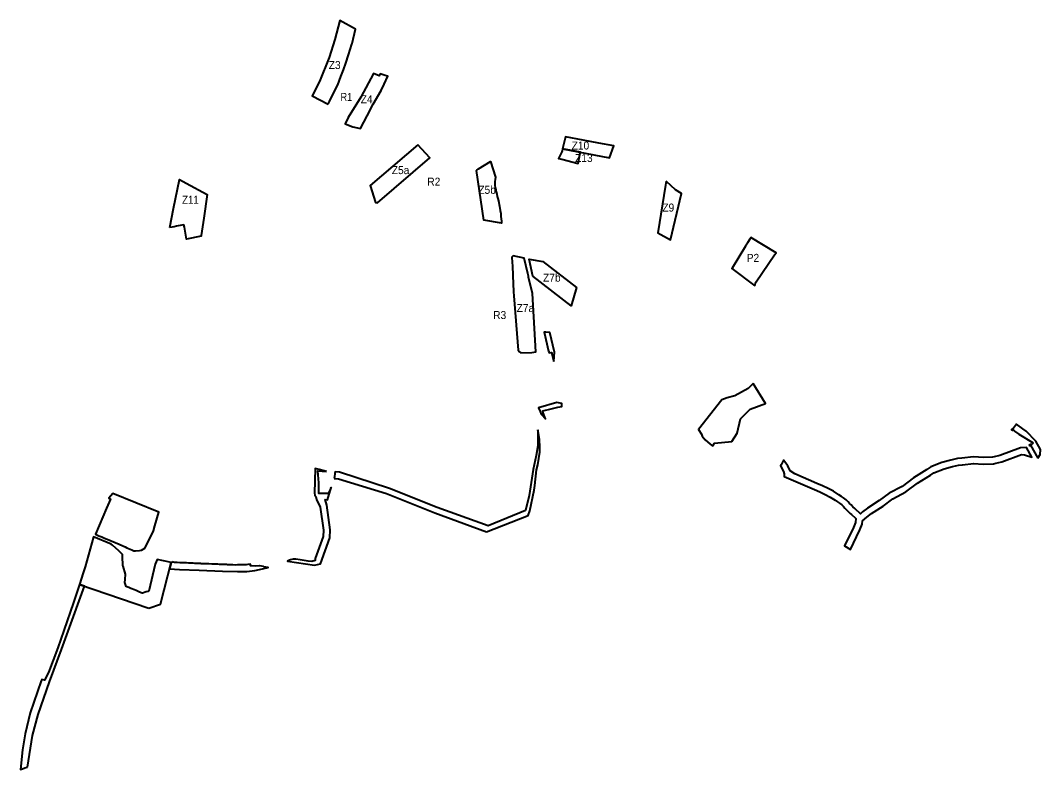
# Model space of a CAD drawing. Extents: x -555426 to -553131, y -1186725 to -1183160.
# Drawn here: x -555426 to -553131, y -1186725 to -1185042 of the extents above; entities that cross this region are included whole.
import ezdxf
from ezdxf.enums import TextEntityAlignment as Align

# ---------------------------------------------------------------- set-up
doc = ezdxf.new("R2010")
doc.units = 0
doc.header["$LTSCALE"] = 7.2
doc.header["$PDMODE"] = 32
doc.header["$PDSIZE"] = 3.6
for name, color, linetype, lineweight in [('12', 7, 'Continuous', 40), ('17', 7, 'Continuous', 40), ('2', 7, 'Continuous', 40), ('48', 7, 'Continuous', 40), ('6', 7, 'Continuous', 40), ('62', 7, 'Continuous', 25), ('8', 7, 'Continuous', 40)]:
    doc.layers.add(name, color=color, linetype=linetype, lineweight=lineweight)
for name, color, linetype in [('59', 7, 'Continuous'), ('60', 7, 'Continuous'), ('61', 7, 'Continuous')]:
    doc.layers.add(name, color=color, linetype=linetype)

msp = doc.modelspace()

# ---------------------------------------------------------------- linework, layer by layer
at = {"layer": '12'}
msp.add_lwpolyline([(-553973.359, -1185402.641), (-553974.35, -1185411.9), (-553991.445, -1185519.302), (-553963.43, -1185534.75), (-553938.9, -1185430.55), (-553951.92, -1185422.15), (-553972.449, -1185403.469)], close=True, dxfattribs=at)
at = {"layer": '17'}
msp.add_lwpolyline([(-554205.92, -1185330.047), (-554207, -1185334.66), (-554207.96, -1185336.64), (-554215.313, -1185351.817), (-554207.47, -1185353.77), (-554170.793, -1185362.901), (-554167.012, -1185343.092), (-554166.009, -1185337.836)], close=True, dxfattribs=at)
at = {"layer": '2'}
for points in [[(-554733.51, -1185230.02), (-554730.2, -1185223.52), (-554717.59, -1185197.71), (-554711.77, -1185186.23), (-554704.88, -1185167.56), (-554699.12, -1185152.43), (-554693.52, -1185137.73), (-554687.65, -1185119.22), (-554679.93, -1185094.89), (-554679.52, -1185093.4), (-554671.85, -1185061.39), (-554707.18, -1185041.55), (-554718.485, -1185084.142), (-554731.329, -1185124.63), (-554753.057, -1185179.2), (-554769.052, -1185211.233)], [(-554688.42, -1185259.67), (-554694.99, -1185274.23), (-554677.59, -1185280.44), (-554660.25, -1185284.19), (-554645.24, -1185255.79), (-554631.94, -1185230), (-554613.87, -1185198.73), (-554607.1, -1185184.92), (-554598.76, -1185166.79), (-554605.12, -1185165.73), (-554616.11, -1185161.44), (-554616.48, -1185161.3), (-554618.25, -1185166.48), (-554630.97, -1185160.97), (-554660.04, -1185213.75)], [(-554531.777, -1185321.491), (-554638.923, -1185412.788), (-554627.182, -1185450.638), (-554622.556, -1185451.394), (-554504.308, -1185350.637)], [(-554399.867, -1185378.779), (-554398.64, -1185377.82), (-554394.81, -1185374.96), (-554368.27, -1185358.89), (-554357.24, -1185393.87), (-554357.73, -1185399.4), (-554358.1, -1185403.56), (-554358.55, -1185407.8), (-554358.24, -1185412.39), (-554357.86, -1185417.02), (-554356.48, -1185422.06), (-554355.39, -1185427.08), (-554354.3, -1185432.1), (-554353.02, -1185437.14), (-554351.77, -1185442.03), (-554350.5, -1185447.06), (-554348.02, -1185459.19), (-554346.15, -1185468.55), (-554345.29, -1185475.74), (-554344.6, -1185481.98), (-554344.16, -1185487.64), (-554343.59, -1185493), (-554343.144, -1185497.196), (-554383.322, -1185490.608)], [(-554305.651, -1185782.363), (-554303.28, -1185786.68), (-554300.2, -1185788.59), (-554275.27, -1185787.98), (-554266.32, -1185786.4), (-554273.88, -1185655.23), (-554282.43, -1185618.58), (-554282.94, -1185616.37), (-554284.34, -1185610.24), (-554292.21, -1185575.92), (-554316.867, -1185570.895), (-554319.852, -1185573.671), (-554319.21, -1185586), (-554318.84, -1185593.32), (-554317.73, -1185614.65), (-554316.26, -1185651.34), (-554315.85, -1185660.44)], [(-554272.647, -1185616.49), (-554281.413, -1185578.266), (-554250.477, -1185583.069), (-554174.425, -1185641.889), (-554187.013, -1185682.721)]]:
    msp.add_lwpolyline(points, close=True, dxfattribs=at)
at = {"layer": '48'}
for p, q in [((-553147.76, -1185990.72), (-553153.84, -1185996.12)), ((-553153.84, -1185996.12), (-553136.76, -1186025.81))]:
    msp.add_line(p, q, dxfattribs=at)
for points in [[(-554225.516, -1185808.234), (-554224.11, -1185787.364), (-554234.745, -1185743.116), (-554244.07, -1185742.37), (-554247.64, -1185742.08), (-554237.39, -1185785.09)], [(-554237.39, -1185785.09), (-554235.75, -1185788.44), (-554231.18, -1185787.69), (-554225.516, -1185808.234)], [(-553777.28, -1185857.816), (-553788.665, -1185868.775), (-553818.407, -1185885.262), (-553836.143, -1185889.543), (-553848.116, -1185894.514), (-553900.68, -1185960.74), (-553893.92, -1185971.59), (-553892.19, -1185976.11), (-553885.57, -1185984.25)], [(-553825.075, -1185988.124), (-553813.195, -1185969.073), (-553806.078, -1185936.966), (-553784.191, -1185915.024), (-553749.515, -1185902.394), (-553777.28, -1185857.816)], [(-554219.04, -1185900.71), (-554260.557, -1185912.173), (-554256.71, -1185920.61), (-554254.1, -1185926.61), (-554244.35, -1185937.42), (-554249.57, -1185923.77), (-554250.31, -1185919.09), (-554231.43, -1185914.6)], [(-554231.43, -1185914.6), (-554219.41, -1185911.75), (-554216.82, -1185911.13), (-554207.981, -1185909.04), (-554207.51, -1185902.62), (-554219.04, -1185900.71)], [(-553136.76, -1186025.81), (-553131.636, -1186017.15), (-553130.875, -1186005.959), (-553141.815, -1185986.942), (-553163.584, -1185965.017), (-553170.649, -1185959.736), (-553185.396, -1185948.905), (-553193.99, -1185961.2)], [(-554261.93, -1185961.69), (-554261.867, -1185997.814), (-554265.332, -1186019.412), (-554272.29, -1186050.65), (-554281.22, -1186109.23), (-554289.524, -1186142.992), (-554373.27, -1186177.71), (-554488.13, -1186136.21), (-554595.17, -1186093.44), (-554707.698, -1186057.015), (-554717.81, -1186056.56), (-554718.22, -1186060.11), (-554719.05, -1186067.25), (-554719.544, -1186071.497)], [(-554377.29, -1186191), (-554283.71, -1186153.97), (-554279.71, -1186143.62), (-554270.02, -1186097.65), (-554268.36, -1186086.78), (-554265, -1186051.94), (-554262.02, -1186040.25), (-554257.45, -1186011.8), (-554256.93, -1185999.75), (-554257.84, -1185983.71), (-554261.93, -1185961.69)], [(-553193.99, -1185961.2), (-553189.33, -1185964.5), (-553179.63, -1185971.75), (-553147.76, -1185990.72)], [(-553885.57, -1185984.25), (-553874.36, -1185993.93), (-553868.12, -1185998.62)], [(-553868.12, -1185998.62), (-553864.032, -1185991.549), (-553825.075, -1185988.124)], [(-554737.11, -1186055.23), (-554753.62, -1186050.71), (-554762.47, -1186048.86), (-554763.69, -1186104.04), (-554763.13, -1186108.53), (-554761.3, -1186111.92), (-554759.33, -1186118.73), (-554750.96, -1186135.85), (-554743.83, -1186187.67), (-554744.21, -1186201.47), (-554762.32, -1186250.8), (-554762.42, -1186255.74), (-554769.94, -1186257.54), (-554778.46, -1186256.89), (-554796.4, -1186253.91), (-554805.74, -1186252.36), (-554812.08, -1186252.63), (-554817.93, -1186254.2), (-554820.52, -1186254.89), (-554825.122, -1186257.297), (-554764.262, -1186265.676)], [(-554764.262, -1186265.676), (-554750.84, -1186263.055), (-554729.283, -1186204.336), (-554728.802, -1186186.849), (-554736.428, -1186131.423), (-554740.112, -1186118.075), (-554734.72, -1186119), (-554726.42, -1186091.6), (-554733.53, -1186104.88), (-554754.02, -1186104.78), (-554754.21, -1186080.59), (-554756.79, -1186053.88), (-554737.11, -1186055.23)], [(-554719.544, -1186071.497), (-554710.393, -1186071.909), (-554602.25, -1186105.03), (-554493.14, -1186148.4), (-554377.29, -1186191)], [(-555084.2, -1186258.4), (-555084.7, -1186260.33), (-555086.13, -1186260.01), (-555089.854, -1186274.456)], [(-554906.96, -1186263.94), (-554913.63, -1186264.75), (-554917.47, -1186265.28), (-554919.39, -1186265.33), (-554927.11, -1186265.47), (-554932.26, -1186265.55), (-554936.56, -1186265.5), (-554937.11, -1186265.47), (-554942.03, -1186265.63), (-554947.66, -1186265.42), (-554953.66, -1186265.32), (-554959.36, -1186264.92), (-554961.69, -1186264.81), (-554964.83, -1186264.67), (-554969.85, -1186264.42), (-554976.07, -1186264.1), (-554978.07, -1186264.16), (-554981.59, -1186263.95), (-554986.25, -1186263.91), (-554987.98, -1186263.78), (-554994.91, -1186263.58), (-555001.35, -1186263.21), (-555004.22, -1186263.18), (-555007.26, -1186263.05), (-555012.37, -1186262.95), (-555013.89, -1186263.01), (-555018.64, -1186262.69), (-555020.77, -1186262.57), (-555022.88, -1186262.45), (-555027.97, -1186262.21), (-555033.35, -1186261.86), (-555037.22, -1186261.67), (-555038.25, -1186261.63), (-555042.62, -1186261.45), (-555045.15, -1186261.2), (-555047.35, -1186261.3), (-555052.31, -1186261.05), (-555057.13, -1186260.95), (-555060.21, -1186260.69), (-555061.43, -1186260.68), (-555067.24, -1186260.4), (-555072.69, -1186260.16), (-555077.96, -1186259.94), (-555079.09, -1186259.62), (-555084.2, -1186258.4)], [(-554937.275, -1186280.483), (-554916.246, -1186280.253), (-554898.31, -1186277.981), (-554881.215, -1186274.099), (-554868.43, -1186271.13), (-554869.06, -1186271.01), (-554877.64, -1186269.36), (-554878.85, -1186269.12), (-554886.77, -1186267.56), (-554887.87, -1186267.31), (-554897.58, -1186268.01), (-554907.83, -1186267.84), (-554906.96, -1186263.94)], [(-555089.854, -1186274.456), (-555067.931, -1186275.384), (-555023.659, -1186277.43), (-554970.608, -1186279.401), (-554937.275, -1186280.483)], [(-555409.6, -1186719.66), (-555398.08, -1186648.64), (-555385.52, -1186601.65), (-555360.47, -1186527.99), (-555332.87, -1186455.38), (-555317.95, -1186413.97), (-555281.216, -1186313.355), (-555292.95, -1186309.355), (-555305.75, -1186349.85), (-555327.86, -1186412.63), (-555341.32, -1186452.09), (-555362.31, -1186507.34), (-555371.26, -1186524.24), (-555374.35, -1186523.58)], [(-555374.35, -1186523.58), (-555377.44, -1186522.92), (-555378.76, -1186526.22), (-555403.3, -1186597.68)], [(-555403.3, -1186597.68), (-555414.63, -1186645.4), (-555420.53, -1186680.78), (-555425.54, -1186725.43), (-555420.84, -1186723.67), (-555415.22, -1186721.67), (-555409.6, -1186719.66)]]:
    msp.add_lwpolyline(points, dxfattribs=at)
for points in [[(-553548.02, -1186159.66), (-553546.182, -1186161.261), (-553546.991, -1186169.987), (-553551.543, -1186181.231), (-553571.668, -1186222.815), (-553558.79, -1186230.64), (-553551.72, -1186216.33), (-553544.71, -1186202.05), (-553537.64, -1186186.86), (-553532.26, -1186173.57), (-553531.6, -1186166.45), (-553521.79, -1186158.06), (-553511.19, -1186150.03), (-553485.32, -1186133.04), (-553463.3, -1186117.12), (-553433.95, -1186101.46), (-553408.08, -1186081.8), (-553378.55, -1186063.63), (-553370.87, -1186058.18), (-553348.08, -1186049.28), (-553328.68, -1186044.22), (-553315.27, -1186040.84), (-553306.3, -1186040.1), (-553306.3, -1186040.1), (-553281.66, -1186037.48), (-553281.66, -1186037.48), (-553259.77, -1186038.75), (-553237.04, -1186038), (-553231.86, -1186036.89), (-553218.26, -1186033.91), (-553173.99, -1186017.29), (-553167.22, -1186018.11), (-553150.76, -1186023.24), (-553162.91, -1186001.77), (-553175.828, -1186001.958), (-553222.523, -1186019.488), (-553235.037, -1186022.23), (-553238.873, -1186023.052), (-553259.583, -1186023.736), (-553282.021, -1186022.434), (-553307.71, -1186025.165), (-553317.736, -1186025.993), (-553332.406, -1186029.69), (-553352.717, -1186034.988), (-553378.046, -1186044.879), (-553386.83, -1186051.112), (-553416.569, -1186069.411), (-553442.07, -1186088.791), (-553471.261, -1186104.366), (-553493.836, -1186120.687), (-553519.846, -1186137.769), (-553531.202, -1186146.372), (-553535.863, -1186150.358), (-553538.103, -1186148.406), (-553546.022, -1186141.348), (-553548.683, -1186138.882), (-553553.043, -1186134.503), (-553557.145, -1186130.6), (-553560.554, -1186127.153), (-553563.838, -1186123.82), (-553568.263, -1186119.334), (-553574.069, -1186114.956), (-553578.7, -1186111.427), (-553584.623, -1186107.599), (-553596.515, -1186099.928), (-553608.823, -1186093.668), (-553621.239, -1186087.362), (-553633.865, -1186082.054), (-553683.475, -1186060.759), (-553694.198, -1186053.632), (-553699.051, -1186042.658), (-553709.22, -1186029.91), (-553714.54, -1186040.11), (-553715.99, -1186043.02), (-553709.24, -1186055.23), (-553707.92, -1186060.73), (-553707.78, -1186066.65), (-553639.73, -1186095.86), (-553627.55, -1186100.98), (-553615.62, -1186107.04), (-553604, -1186112.95), (-553592.76, -1186120.2), (-553587.33, -1186123.71), (-553583.13, -1186126.91), (-553578.17, -1186130.65), (-553574.52, -1186134.35), (-553571.23, -1186137.69), (-553567.65, -1186141.31), (-553563.53, -1186145.23), (-553559.1, -1186149.68), (-553556.11, -1186152.45)], [(-555185.99, -1186226.72), (-555175.06, -1186231.77), (-555170.16, -1186234.03), (-555166.5, -1186233.72), (-555157.32, -1186232.94), (-555153.01, -1186232.57), (-555146, -1186227.85), (-555144.69, -1186226.97), (-555126.25, -1186188.5), (-555123.11, -1186177.66), (-555114.26, -1186147.16), (-555217.36, -1186104.58), (-555226.45, -1186115.68), (-555223.12, -1186117.41), (-555232.18, -1186137.72), (-555256.91, -1186196.5), (-555248.77, -1186199.76), (-555242.74, -1186202.33), (-555236.71, -1186204.91), (-555230.2, -1186207.64), (-555212.56, -1186215.1), (-555203.72, -1186218.85), (-555194.89, -1186222.61), (-555190.05, -1186224.85)], [(-555136.764, -1186362.594), (-555110.731, -1186353.98), (-555101.91, -1186321.23), (-555086.13, -1186260.01), (-555093.4, -1186258.38), (-555100.06, -1186256.89), (-555107.79, -1186255.16), (-555114.53, -1186253.65), (-555117.88, -1186252.9), (-555122.79, -1186264.03), (-555136.85, -1186324.41), (-555138.36, -1186325.06), (-555142.52, -1186326.28), (-555150.68, -1186328.68), (-555151.71, -1186328.98), (-555157.95, -1186326.36), (-555165.36, -1186323.24), (-555169.27, -1186321.6), (-555177.22, -1186318.25), (-555181.71, -1186316.36), (-555186.26, -1186314.45), (-555187.71, -1186313.84), (-555190.76, -1186304.59), (-555190.1, -1186297.86), (-555188.93, -1186285.88), (-555194.7, -1186268.11), (-555195.22, -1186267.63), (-555195.64, -1186245.84), (-555195.72, -1186241.89), (-555197.18, -1186240.55), (-555204.2, -1186234.11), (-555218.31, -1186221.15), (-555221.4, -1186218.64), (-555261.28, -1186202.32), (-555279.68, -1186269.64), (-555284.72, -1186283.32), (-555292.95, -1186309.355)]]:
    msp.add_lwpolyline(points, close=True, dxfattribs=at)
for p in [(-553193.99, -1185961.2), (-553153.84, -1185996.12)]:
    msp.add_point(p, dxfattribs=at)
at = {"layer": '6'}
msp.add_lwpolyline([(-554205.92, -1185330.047), (-554100.379, -1185350.644), (-554090.82, -1185323.71), (-554124.84, -1185317.69), (-554160.01, -1185310.95), (-554199.59, -1185303)], close=True, dxfattribs=at)
at = {"layer": '62'}
for points in [[(-554707.18, -1185041.55), (-554671.85, -1185061.39), (-554679.52, -1185093.4), (-554679.93, -1185094.89), (-554687.65, -1185119.22), (-554693.52, -1185137.73), (-554699.12, -1185152.43), (-554704.88, -1185167.56), (-554711.77, -1185186.23), (-554717.59, -1185197.71), (-554730.2, -1185223.52), (-554733.51, -1185230.02), (-554769.052, -1185211.233), (-554753.057, -1185179.2), (-554731.329, -1185124.63), (-554718.485, -1185084.142)], [(-554677.59, -1185280.44), (-554660.25, -1185284.19), (-554645.24, -1185255.79), (-554631.94, -1185230), (-554613.87, -1185198.73), (-554607.1, -1185184.92), (-554598.76, -1185166.79), (-554605.12, -1185165.73), (-554616.11, -1185161.44), (-554616.48, -1185161.3), (-554618.25, -1185166.48), (-554630.97, -1185160.97), (-554660.04, -1185213.75), (-554688.42, -1185259.67), (-554694.99, -1185274.23)], [(-554205.92, -1185330.047), (-554100.379, -1185350.644), (-554090.82, -1185323.71), (-554124.84, -1185317.69), (-554160.01, -1185310.95), (-554199.59, -1185303)], [(-554531.777, -1185321.491), (-554638.923, -1185412.788), (-554627.182, -1185450.638), (-554622.556, -1185451.394), (-554504.308, -1185350.637)], [(-554399.867, -1185378.779), (-554398.64, -1185377.82), (-554394.81, -1185374.96), (-554368.27, -1185358.89), (-554357.24, -1185393.87), (-554357.73, -1185399.4), (-554358.1, -1185403.56), (-554358.55, -1185407.8), (-554358.24, -1185412.39), (-554357.86, -1185417.02), (-554356.48, -1185422.06), (-554355.39, -1185427.08), (-554354.3, -1185432.1), (-554353.02, -1185437.14), (-554351.77, -1185442.03), (-554350.5, -1185447.06), (-554348.02, -1185459.19), (-554346.15, -1185468.55), (-554345.29, -1185475.74), (-554344.6, -1185481.98), (-554344.16, -1185487.64), (-554343.59, -1185493), (-554343.144, -1185497.196), (-554383.322, -1185490.608)], [(-555089.21, -1185507), (-555081.04, -1185464.34), (-555067.367, -1185399.402), (-555052.93, -1185407.202), (-555005.1, -1185432.97), (-555013.13, -1185486.02), (-555019.08, -1185525.33), (-555019.241, -1185526.435), (-555051.7, -1185532.91), (-555053.44, -1185523.9), (-555056.79, -1185506.46), (-555057.82, -1185501.14), (-555062.21, -1185501.96), (-555074.79, -1185504.31), (-555079.88, -1185505.26), (-555084.52, -1185506.13)], [(-553938.9, -1185430.55), (-553951.92, -1185422.15), (-553972.449, -1185403.469), (-553973.359, -1185402.641), (-553974.35, -1185411.9), (-553991.445, -1185519.302), (-553963.43, -1185534.75), (-553947.05, -1185465.171)], [(-553771.93, -1185632.13), (-553770.83, -1185628.82), (-553729.23, -1185568.43), (-553726.01, -1185563.76), (-553782.49, -1185529.43), (-553782.81, -1185529.95), (-553784.83, -1185533.39), (-553789.98, -1185541.71), (-553790.41, -1185542.52), (-553794.42, -1185548.98), (-553824.8, -1185598.76), (-553825.09, -1185599.26), (-553773.82, -1185637.86)], [(-554273.88, -1185655.23), (-554266.32, -1185786.4), (-554275.27, -1185787.98), (-554300.2, -1185788.59), (-554303.28, -1185786.68), (-554305.651, -1185782.363), (-554315.85, -1185660.44), (-554316.26, -1185651.34), (-554317.73, -1185614.65), (-554318.84, -1185593.32), (-554319.21, -1185586), (-554319.852, -1185573.671), (-554316.867, -1185570.895), (-554292.21, -1185575.92), (-554284.34, -1185610.24), (-554282.94, -1185616.37), (-554282.43, -1185618.58)], [(-554272.647, -1185616.49), (-554281.413, -1185578.266), (-554250.477, -1185583.069), (-554174.425, -1185641.889), (-554187.013, -1185682.721)]]:
    msp.add_lwpolyline(points, close=True, dxfattribs=at)
msp.add_lwpolyline([(-554205.92, -1185330.047), (-554207, -1185334.66), (-554207.96, -1185336.64), (-554215.313, -1185351.817), (-554207.47, -1185353.77), (-554170.793, -1185362.901), (-554167.012, -1185343.092), (-554166.009, -1185337.836)], dxfattribs=at)
at = {"layer": '8'}
msp.add_line((-553773.82, -1185637.86), (-553771.93, -1185632.13), dxfattribs=at)
msp.add_lwpolyline([(-555089.21, -1185507), (-555081.04, -1185464.34), (-555067.367, -1185399.402), (-555052.93, -1185407.202), (-555005.1, -1185432.97), (-555013.13, -1185486.02), (-555019.08, -1185525.33), (-555019.241, -1185526.435), (-555051.7, -1185532.91), (-555053.44, -1185523.9), (-555056.79, -1185506.46), (-555057.82, -1185501.14), (-555062.21, -1185501.96), (-555074.79, -1185504.31), (-555079.88, -1185505.26), (-555084.52, -1185506.13)], close=True, dxfattribs=at)
msp.add_lwpolyline([(-553771.93, -1185632.13), (-553770.83, -1185628.82), (-553729.23, -1185568.43), (-553726.01, -1185563.76), (-553782.49, -1185529.43), (-553782.81, -1185529.95), (-553784.83, -1185533.39), (-553789.98, -1185541.71), (-553790.41, -1185542.52), (-553794.42, -1185548.98), (-553824.8, -1185598.76), (-553825.09, -1185599.26), (-553773.82, -1185637.86)], dxfattribs=at)

# ---------------------------------------------------------------- texts
at = {"layer": '59'}
for s, width, p in [('R1', 0.85, (-554692.338, -1185222.522)), ('R2', 0.95, (-554495.666, -1185412.962)), ('R3', 0.95, (-554347.47, -1185712.82))]:
    msp.add_text(s, height=18, dxfattribs=dict(at, width=width)).set_placement(p, align=Align.CENTER)
at = {"layer": '60'}
for s, width, p in [('Z3', 0.95, (-554718.655, -1185150.848)), ('Z4', 0.95, (-554646.684, -1185227.631)), ('Z10', 0.95, (-554165.892, -1185331.712)), ('Z13', 0.95, (-554158.125, -1185359.758)), ('Z5a', 0.95, (-554570.399, -1185387.01)), ('Z5b', 0.95, (-554375.806, -1185431.33)), ('Z11', 0.9, (-555043.081, -1185453.571)), ('Z9', 0.95, (-553968.262, -1185471.234)), ('Z7b', 0.95, (-554230.213, -1185628.728)), ('Z7a', 0.95, (-554289.726, -1185697.027))]:
    msp.add_text(s, height=18, dxfattribs=dict(at, width=width)).set_placement(p, align=Align.CENTER)
at = {"layer": '61', "width": 0.95}
msp.add_text('P2', height=18, dxfattribs=at).set_placement((-553777.872, -1185584.292), align=Align.CENTER)

doc.saveas('drawing.dxf')
